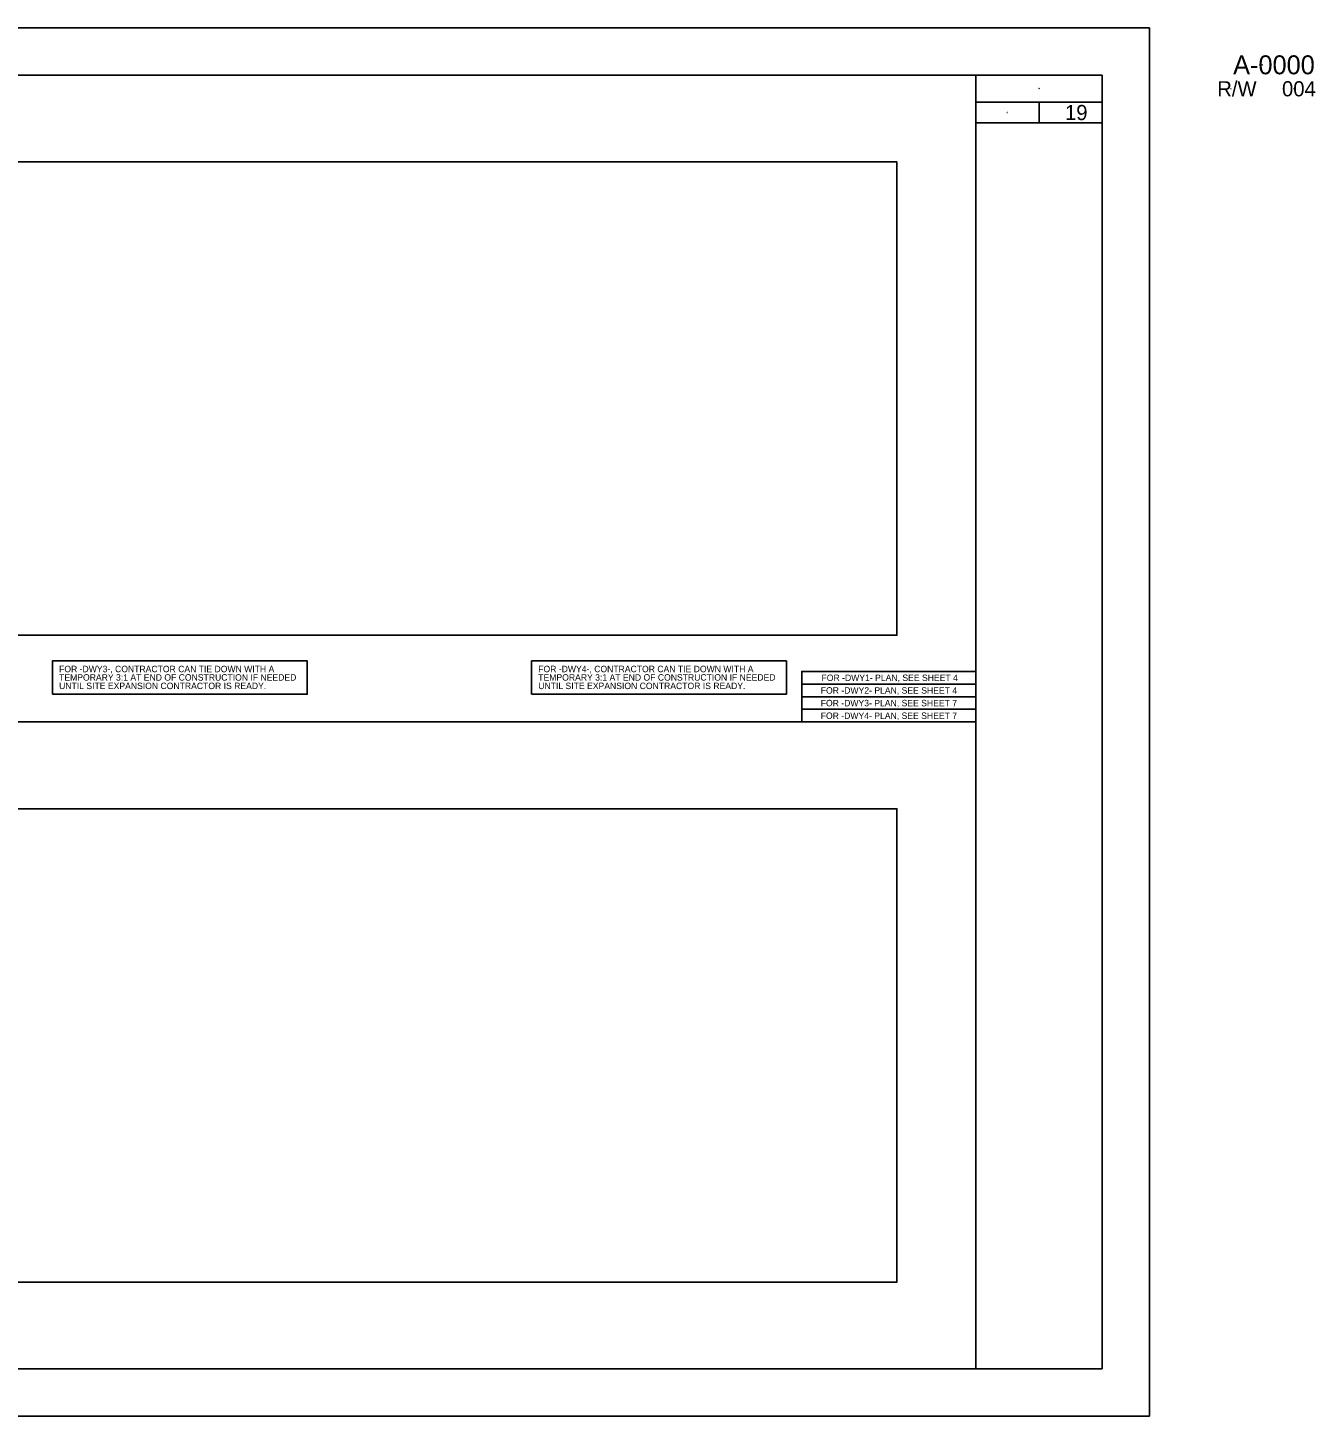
# Model space of a CAD drawing. Extents: x -0.19 to 3.05, y 0 to 1.83.
# Drawn here: x 1.352 to 3.052, y 0 to 1.833 of the extents above; entities that cross this region are included whole.
import ezdxf

# ---------------------------------------------------------------- set-up
doc = ezdxf.new("R2010")
doc.units = 0
for name, color, linetype in [('P_NCDOT_Vertical_Profile_Grade_Curve_Data_Label', 7, 'Continuous'), ('P_NCDOT_Vertical_Profile_Grade_Sheet_Grid_Border', 7, 'Continuous'), ('P_NCDOT_Vertical_Profile_Grade_Sheet_Station_Label', 7, 'Continuous'), ('Sheet_Grid_Middle', 7, 'Continuous'), ('Sheet_Grid_Minor', 7, 'Continuous')]:
    doc.layers.add(name, color=color, linetype=linetype)

msp = doc.modelspace()

# ---------------------------------------------------------------- linework, layer by layer
at = {"layer": 'P_NCDOT_Vertical_Profile_Grade_Sheet_Grid_Border'}
for centre in [(2.9826, 1.7844), (2.9409, 1.7528), (3.0243, 1.7528)]:
    msp.add_circle(centre, 0.0001, dxfattribs=at)
at = {"layer": 'P_NCDOT_Vertical_Profile_Grade_Sheet_Station_Label'}
for points in [[(1.3849, 0.9532), (1.7214, 0.9532), (1.7214, 0.9974), (1.3849, 0.9974)], [(2.0175, 0.9532), (2.354, 0.9532), (2.354, 0.9974), (2.0175, 0.9974)], [(2.3742, 0.9668), (2.6041, 0.9668), (2.6041, 0.9835), (2.3742, 0.9835)], [(2.3742, 0.9501), (2.6041, 0.9501), (2.6041, 0.9668), (2.3742, 0.9668)], [(2.3742, 0.9334), (2.6041, 0.9334), (2.6041, 0.9501), (2.3742, 0.9501)], [(2.3742, 0.9167), (2.6041, 0.9167), (2.6041, 0.9334), (2.3742, 0.9334)]]:
    msp.add_lwpolyline(points, close=True, dxfattribs=at)
at = {"layer": 'Sheet_Grid_Middle'}
for p, q in [((2.7708, 1.7708), (0.0625, 1.7708)), ((2.6041, 0.0625), (2.6042, 1.7708)), ((2.7708, 0.0625), (2.7708, 1.7708)), ((2.7708, 1.7351), (2.6042, 1.7351)), ((2.6875, 1.7076), (2.6875, 1.7351)), ((2.7708, 1.7076), (2.6042, 1.7076)), ((2.6041, 0.9167), (0.0625, 0.9167)), ((0.0625, 0.0625), (2.7708, 0.0625))]:
    msp.add_line(p, q, dxfattribs=at)
msp.add_circle((2.6042, 1.7076), 0.0001, dxfattribs=at)
at = {"layer": 'Sheet_Grid_Minor'}
for p, q in [((0, 1.8333), (2.8333, 1.8333)), ((2.8333, 0), (2.8333, 1.8333)), ((0, 0), (2.8333, 0))]:
    msp.add_line(p, q, dxfattribs=at)
for points in [[(0.1667, 1.0312), (2.5, 1.0312), (2.5, 1.6562), (0.1667, 1.6562)], [(0.1666, 0.8021), (2.5, 0.8021), (2.5, 0.1771), (0.1666, 0.1771)]]:
    msp.add_lwpolyline(points, close=True, dxfattribs=at)
for centre in [(2.6875, 1.753), (2.6458, 1.7214), (2.7292, 1.7214)]:
    msp.add_circle(centre, 0.0001, dxfattribs=at)

# ---------------------------------------------------------------- texts
at = {"layer": 'P_NCDOT_Vertical_Profile_Grade_Curve_Data_Label'}
for s, p in [('FOR -DWY3-, CONTRACTOR CAN TIE DOWN WITH A ', (1.3938, 0.9824)), ('FOR -DWY4-, CONTRACTOR CAN TIE DOWN WITH A ', (2.0264, 0.9824)), ('TEMPORARY 3:1 AT END OF CONSTRUCTION IF NEEDED ', (1.3938, 0.9713)), ('TEMPORARY 3:1 AT END OF CONSTRUCTION IF NEEDED ', (2.0264, 0.9713)), ('FOR -DWY1- PLAN, SEE SHEET 4', (2.4004, 0.9708)), ('UNTIL SITE EXPANSION CONTRACTOR IS READY. ', (1.3938, 0.9601)), ('UNTIL SITE EXPANSION CONTRACTOR IS READY. ', (2.0264, 0.9601)), ('FOR -DWY2- PLAN, SEE SHEET 4', (2.3994, 0.9541)), ('FOR -DWY3- PLAN, SEE SHEET 7', (2.3993, 0.9374)), ('FOR -DWY4- PLAN, SEE SHEET 7', (2.3993, 0.9207))]:
    msp.add_text(s, height=0.0085, dxfattribs=at).set_placement(p)
at = {"layer": 'P_NCDOT_Vertical_Profile_Grade_Sheet_Grid_Border'}
for s, height, p in [('A-0000', 0.025, (2.9438, 1.7719)), ('R/W', 0.02, (2.9228, 1.7428)), ('004', 0.02, (3.0083, 1.7428)), ('19', 0.02, (2.7218, 1.7114))]:
    msp.add_text(s, height=height, dxfattribs=at).set_placement(p)

doc.saveas('drawing.dxf')
